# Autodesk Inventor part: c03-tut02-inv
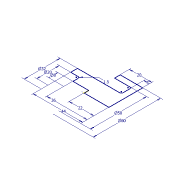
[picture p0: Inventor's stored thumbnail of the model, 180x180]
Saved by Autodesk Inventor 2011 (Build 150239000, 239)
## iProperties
Created: 2010-01
Part Number: c03-tut02-inv
Document SubType Name: Modeling
Designer: CADSoft
Density: 1 g/cm^3
Author: CADSoft
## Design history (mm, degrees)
sketch "Sketch1"
  geometry: L1 (22, 0)-(22, 30); L2 (22, 30)-(2, 30); L3 (2, 30)-(2, 25); L4 (2, 25)-(15.5, 25); L5 (17, 23.5)-(17, 17.5); L6 (15.5, 16)-(-22, 16); L7 (-22, 16)-(-22, 10); L8 (-22, 10)-(-15.5, 10); L9 (-14, 8.5)-(-14, 4); L10 (-14, 4)-(0, 4); L11 (0, 4)-(0, 0); L12 (0, 0)-(22, 0); A1 r 1.5 centre (-15.5, 8.5) between (-14, 8.5) and (-15.5, 10); A2 r 1.5 centre (15.5, 23.5) between (17, 23.5) and (15.5, 25); A3 r 1.5 centre (15.5, 17.5) between (15.5, 16) and (17, 17.5); 2 further points
  constraints: 24 end point, 6 point on circle, 6 tangent, 3 centre point, 2 coincident, 2 equal radius, 2 vertical, 1 horizontal, 1 other
  dimensions: "d0" = 8 diameter of L10 L12; "d1" = 20 diameter of L8 L12; "d2" = 32 diameter of L6 L12; "d3" = 50 diameter of L4 L12; "d5" = 60 diameter of L2 L12; "d6" = 5 distance between parallel lines of L5 L1; "d7" = 20 distance of L1.end L2.end; "d8" = 22 distance of L11.end L1.start; "d9" = 36 distance between parallel lines of L9 L1; "d10" = 44 distance between parallel lines of L7 L1; "d11" = 1.5 radius of A1
